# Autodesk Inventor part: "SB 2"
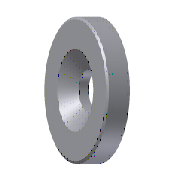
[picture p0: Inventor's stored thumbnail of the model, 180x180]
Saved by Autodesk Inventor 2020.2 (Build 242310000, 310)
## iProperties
Manager: www.cadconsulting.pl
Company: Fabian Stasiak CAD Consulting
Created: 2014-02
Part Number: "SB 2"
Material: DIN 1.2312
Description: Spacer washer for ejector plates
Document SubType Name: Modeling
Designer: F.Stasiak
Standard Revision: 1
Manufacturer: DME
Language: pl-PL
Size Designation: " 2"
Categories: <MemberInstance><Categories><Category DisplayName="Forma wtryskowa" InternalName="349578f2-f4d4-4954-8c09-8e99297a61c0" Mnemonic="MOLD"><Category DisplayName="A
Density: 7.85 g/cm^3
Appearance: Domyślna
Catalog Web Link: www.expertbooks.pl
IsCustomPart: 0
Author: F.Stasiak
Subject: Zbiór ćwiczeń. Autodesk Inventor 2020. Kurs Professional
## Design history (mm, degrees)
sketch "Sketch1"
  geometry: L1 (0, -0.8)-(0, 4.8) reference; L2 (2.25, 1.5)-(4.75, 4); L3 (4.75, 4)-(8, 4); L4 (8, 4)-(8, 0); L5 (8, 0)-(2.25, 0); L6 (2.25, 0)-(2.25, 1.5); 1 further point
  constraints: 10 end point, 4 perpendicular, 1 horizontal alignment
  dimensions: "d0" = 45 deg angle of L2 L1 (= A_); "d1" = 9.5 diameter of L2.end L1 (= Sink_Dia); "d2" = 16 diameter of L4 L1 (= D); "d3" = 4 distance between parallel lines of L5 L3 (= H1); "d4" = 4.5 diameter of L6 L1 (= d_)
revolve "Revolution1" sketch "Sketch1" stored, may be unused: angle "d5" = 90 deg
chamfer "Chamfer1" distance "d6" = 0.3; stored, may be unused: second distance "d7" = 2, angle "d8" = 45 deg
body "Solid1"
other parameters: "D" = 16 [user parameter; used in 1 equation term], "H1" = 4 [user parameter; used in 1 equation term], "d_" = 4.5 [user parameter; used in 1 equation term], "Sink_Dia" = 9.5 [user parameter; used in 1 equation term], "d9" = 0, "d10" = 0, "d11" = 0, "A_" = 45 deg [user parameter; used in 1 equation term]
